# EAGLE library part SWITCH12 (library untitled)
Drehschalter begrenzbar, DDR-Version kaskadierbar
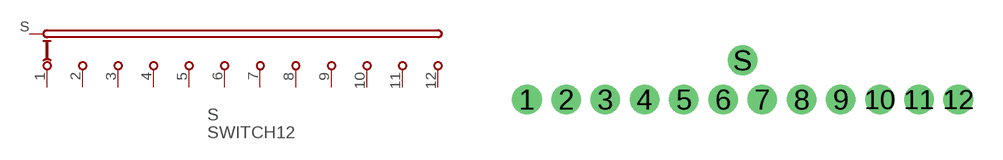
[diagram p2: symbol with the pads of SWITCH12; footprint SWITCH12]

Designator prefix S

## SWITCH12  [SWITCH12]
1  1  pas
2  2  pas
3  3  pas
4  4  pas
5  5  pas
6  6  pas
7  7  pas
8  8  pas
9  9  pas
10  10  pas
11  11  pas
12  12  pas
S  S  pas

## Footprint SWITCH12 (pad centres in mm)
drill 1 round: 1 -11,-1; 2 -9,-1; 3 -7,-1; 4 -5,-1; 5 -3,-1; 6 -1,-1; 7 1,-1; 8 3,-1; 9 5,-1; 10 7,-1; 11 9,-1; 12 11,-1; S 0,1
